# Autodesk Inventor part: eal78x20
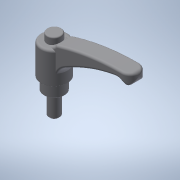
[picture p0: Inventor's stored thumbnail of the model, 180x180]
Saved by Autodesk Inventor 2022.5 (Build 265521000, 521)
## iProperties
Created: 2016-12
Part Number: eal78x20
Material: 一般
Document SubType Name: Modeling
Designer: imaocorp
Density: 1 g/cm^3
Appearance: 既定
Author: imaocorp
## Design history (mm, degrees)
node "eal78x20.x_t1"
node "eal78x20"
node "Base1"
